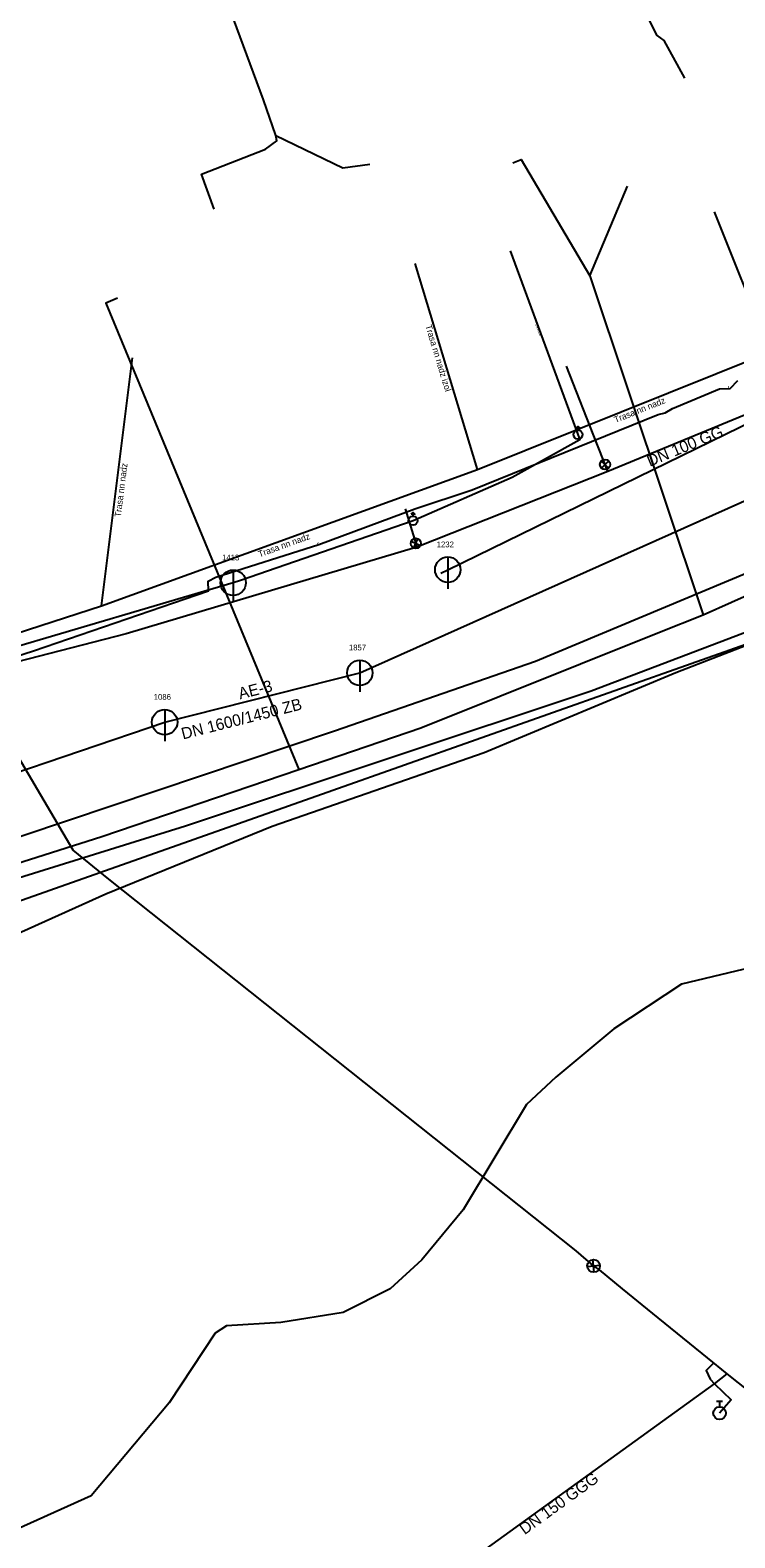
# Model space of a CAD drawing. Extents: x -493753 to -49291, y -1127285 to -112662.
# Drawn here: x -493148.8 to -493093.4, y -1126714.4 to -1126595.6 of the extents above; entities that cross this region are included whole.
import ezdxf

# ---------------------------------------------------------------- set-up
doc = ezdxf.new("R2010")
doc.units = 0
for name, color, linetype in [('Vrstva 1', 7, 'Continuous'), ('Vrstva 15', 7, 'Continuous'), ('Vrstva 17', 7, 'Continuous'), ('Vrstva 19', 7, 'Continuous'), ('Vrstva 20', 7, 'Continuous'), ('Vrstva 22', 7, 'Continuous'), ('Vrstva 24', 7, 'Continuous'), ('Vrstva 25', 7, 'Continuous'), ('Vrstva 26', 7, 'Continuous'), ('Vrstva 39', 7, 'Continuous'), ('Vrstva 5', 7, 'Continuous'), ('Vrstva 6', 7, 'Continuous'), ('Vrstva 9', 7, 'Continuous')]:
    doc.layers.add(name, color=color, linetype=linetype)

# ---------------------------------------------------------------- blocks, each defined once
blk = doc.blocks.new('_UZAVE')
at = {"layer": 'Vrstva 1'}
for p, q in [((-0.035, -0.035), (0.035, 0.035)), ((0.035, -0.035), (-0.035, 0.035))]:
    blk.add_line(p, q, dxfattribs=at)
for radius in [0.05, 0.0025]:
    blk.add_circle((0, 0), radius, dxfattribs=at)
blk = doc.blocks.new('_UZAV0')
at = {"layer": 'Vrstva 1'}
for p, q in [((-0.035, -0.035), (0.035, 0.035)), ((0.035, -0.035), (-0.035, 0.035))]:
    blk.add_line(p, q, dxfattribs=at)
for radius in [0.05, 0.0025]:
    blk.add_circle((0, 0), radius, dxfattribs=at)
blk = doc.blocks.new('_HYDRA')
at = {"layer": 'Vrstva 1'}
for p, q in [((-0.0225, 0.095), (0.0225, 0.095)), ((0, 0.095), (0, 0.05))]:
    blk.add_line(p, q, dxfattribs=at)
blk.add_circle((0, 0), 0.05, dxfattribs=at)
blk = doc.blocks.new('_SACHT')
at = {"layer": 'Vrstva 1'}
blk.add_line((0, 0.035), (0, 0.05), dxfattribs=at)
blk.add_lwpolyline([(-0.015, 0.05), (0, 0.065), (0.015, 0.05), (0.0025, 0.05)], close=True, dxfattribs=at)
blk.add_circle((0, 0), 0.035, dxfattribs=at)
blk = doc.blocks.new('_SACH0')
at = {"layer": 'Vrstva 1'}
blk.add_line((0, 0.05), (0, -0.075), dxfattribs=at)
blk.add_circle((0, 0), 0.05, dxfattribs=at)

msp = doc.modelspace()

# ---------------------------------------------------------------- linework, layer by layer
at = {"layer": 'Vrstva 1'}
for q in [(-493101.8, -1126607.9), (-493095.87, -1126641.67)]:
    msp.add_line((-493104.79, -1126614.96), q, dxfattribs=at)
for points in [[(-493386.97, -1126735.58), (-493385.48, -1126734.62), (-493337.07, -1126719.76), (-493332.99, -1126718.51), (-493329.52, -1126722.33), (-493310.17, -1126716.12), (-493297.1, -1126711.97), (-493263.47, -1126701.76), (-493238.75, -1126693.15), (-493207.17, -1126683.67), (-493191.4, -1126678.95), (-493125, -1126655.47), (-493062.97, -1126633.54), (-492997.53, -1126590.18)], [(-493110.83, -1126606.06), (-493110.18, -1126605.8), (-493104.79, -1126614.96)], [(-493141.96, -1126616.73), (-493142.88, -1126617.12), (-493127.68, -1126653.85)], [(-493385.61, -1126724.05), (-493194.98, -1126660.12), (-493187.12, -1126657.48), (-493186.67, -1126658.59), (-493182.04, -1126669.95), (-493181.8, -1126670.54), (-493154.52, -1126662.73), (-493143.18, -1126659.14), (-493127.68, -1126653.85), (-493118.08, -1126650.58), (-493099.29, -1126643.04), (-493095.87, -1126641.67), (-493086.94, -1126637.67)]]:
    msp.add_lwpolyline(points, dxfattribs=at)
at = {"layer": 'Vrstva 15'}
for p, q in [((-493115.96, -1126638.11), (-493046.27, -1126604.06)), ((-493122.88, -1126646.24), (-493045.09, -1126611.4)), ((-493111.06, -1126612.99), (-493105.71, -1126627.47)), ((-493118.69, -1126634.25), (-493132.28, -1126638.97)), ((-493132.28, -1126638.97), (-493132.85, -1126639.14)), ((-493116.5, -1126638.38), (-493115.96, -1126638.11)), ((-493132.85, -1126639.14), (-493171.26, -1126650.48)), ((-493138.24, -1126650.12), (-493122.88, -1126646.24)), ((-493211.56, -1126675.07), (-493138.24, -1126650.12))]:
    msp.add_line(p, q, dxfattribs=at)
msp.add_lwpolyline([(-493105.71, -1126627.47), (-493105.56, -1126627.88), (-493110.88, -1126630.84), (-493118.69, -1126634.25)], dxfattribs=at)
at = {"layer": 'Vrstva 20'}
for p, q in [((-493094.98, -1126609.92), (-493090.33, -1126621.6)), ((-493104.23, -1126628.16), (-493106.62, -1126622.08)), ((-493091.16, -1126703.69), (-493093.97, -1126701.44))]:
    msp.add_line(p, q, dxfattribs=at)
for points in [[(-493174.97, -1126671), (-493168.95, -1126668.59), (-493150.92, -1126662.76), (-493136.6, -1126658.3), (-493104.67, -1126647.66), (-493085.83, -1126640.49), (-493075.06, -1126636.63), (-493066.87, -1126632.41), (-493057.12, -1126625.67), (-493040.16, -1126614.7), (-493027.86, -1126606.78), (-493012.63, -1126597.22), (-493006.68, -1126593.57), (-492997.84, -1126587.96), (-492995.32, -1126586.25), (-492988.81, -1126582.57), (-492979.95, -1126576.81), (-492978.81, -1126576)], [(-493104.48, -1126692.95), (-493105.85, -1126691.77), (-493142.64, -1126662.49), (-493145.44, -1126660.21), (-493155.3, -1126643.44), (-493158.9, -1126637.17), (-493179.3, -1126603.57)], [(-493085.26, -1126622.7), (-493089.17, -1126624.53), (-493103.36, -1126630.39), (-493118.4, -1126636.33), (-493141.27, -1126643.17), (-493154.23, -1126646.51)], [(-493103.36, -1126630.39), (-493103.58, -1126629.83), (-493104.23, -1126628.16)], [(-493119.3, -1126633.31), (-493118.47, -1126636.04), (-493118.4, -1126636.33)], [(-493093.97, -1126701.44), (-493095.52, -1126700.19), (-493099.83, -1126696.7), (-493102.2, -1126694.76), (-493104.01, -1126693.25), (-493104.48, -1126692.95)], [(-493095.03, -1126700.59), (-493095.61, -1126701.2), (-493095.31, -1126701.88), (-493094.96, -1126702.23), (-493093.66, -1126703.5), (-493094.57, -1126704.55)], [(-493119.65, -1126720.09), (-493094.96, -1126702.23), (-493093.97, -1126701.44)]]:
    msp.add_lwpolyline(points, dxfattribs=at)
at = {"layer": 'Vrstva 25'}
msp.add_lwpolyline([(-493164.43, -1126646.67), (-493163.94, -1126647.33), (-493163.37, -1126647.77), (-493156.2, -1126645.58), (-493155.46, -1126646.71), (-493148.57, -1126644.5), (-493134.79, -1126639.78), (-493134.82, -1126639.02), (-493134.2, -1126638.71), (-493126.11, -1126636.12), (-493118.54, -1126633.31), (-493114.04, -1126631.81), (-493099.4, -1126625.88), (-493098.84, -1126625.76), (-493098.28, -1126625.42), (-493094.57, -1126623.87), (-493093.74, -1126623.83), (-493093.12, -1126623.22)], dxfattribs=at)
at = {"layer": 'Vrstva 26'}
for p, q in [((-493093.86, -1126623.7), (-493093.83, -1126623.71)), ((-493126.2, -1126636), (-493126.19, -1126636.03))]:
    msp.add_line(p, q, dxfattribs=at)
at = {"layer": 'Vrstva 39'}
for points in [[(-493106.41, -1126581.97), (-493105.81, -1126583.16), (-493099.52, -1126596.02), (-493098.96, -1126596.44), (-493097.32, -1126599.39)], [(-493129.5, -1126603.92), (-493130.46, -1126601.1), (-493133.09, -1126594.02), (-493134.58, -1126590.32)], [(-493134.35, -1126609.71), (-493135.34, -1126606.95), (-493130.31, -1126605), (-493129.42, -1126604.33), (-493129.5, -1126603.92)], [(-493129.5, -1126603.92), (-493124.21, -1126606.47), (-493122.1, -1126606.16)], [(-493156.38, -1126661.38), (-493124.88, -1126650.8), (-493109.06, -1126645.32), (-493090.65, -1126637.63), (-493079.53, -1126633.19)], [(-493081.08, -1126639.68), (-493098.01, -1126646.24), (-493113.1, -1126652.55), (-493129.78, -1126658.33), (-493142.88, -1126663.67), (-493151.41, -1126667.51), (-493153.5, -1126667.92), (-493155.32, -1126667.23)]]:
    msp.add_lwpolyline(points, dxfattribs=at)
at = {"layer": 'Vrstva 5'}
for points in [[(-493113.63, -1126630.23), (-493118.53, -1126613.99)], [(-493113.63, -1126630.23), (-493087.29, -1126619.65)], [(-493143.22, -1126640.97), (-493140.77, -1126621.43)], [(-493143.22, -1126640.97), (-493113.63, -1126630.23)], [(-493173.25, -1126650.69), (-493143.22, -1126640.97)]]:
    msp.add_lwpolyline(points, dxfattribs=at)
at = {"layer": 'Vrstva 6'}
msp.add_lwpolyline([(-493089.02, -1126668.7), (-493097.55, -1126670.77), (-493102.89, -1126674.28), (-493107.46, -1126678.08), (-493109.76, -1126680.24), (-493114.75, -1126688.53), (-493118.01, -1126692.46), (-493120.49, -1126694.75), (-493124.18, -1126696.61), (-493129.09, -1126697.4), (-493133.38, -1126697.66), (-493134.27, -1126698.24), (-493137.89, -1126703.73), (-493144.02, -1126711.06), (-493158.37, -1126717.52), (-493159.88, -1126717.4)], dxfattribs=at)

# ---------------------------------------------------------------- block references
at = {"layer": 'Vrstva 17'}
for name, p, xscale, yscale in [('_SACHT', (-493105.71, -1126627.47), 9.998750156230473, 9.998750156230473), ('_SACHT', (-493118.69, -1126634.25), 9.998750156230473, 9.998750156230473), ('_SACH0', (-493115.96, -1126638.11), 19.997500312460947, 19.997500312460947), ('_SACH0', (-493132.85, -1126639.14), 19.997500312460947, 19.997500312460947), ('_SACH0', (-493122.88, -1126646.24), 19.997500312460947, 19.997500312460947), ('_SACH0', (-493138.24, -1126650.12), 19.997500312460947, 19.997500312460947)]:
    msp.add_blockref(name, p, dxfattribs=dict(at, xscale=xscale, yscale=yscale))
at = {"layer": 'Vrstva 22'}
for name, p, xscale, yscale in [('_UZAV0', (-493103.58, -1126629.83), 7.999000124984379, 7.999000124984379), ('_HYDRA', (-493094.57, -1126704.55), 9.998750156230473, 9.998750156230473)]:
    msp.add_blockref(name, p, dxfattribs=dict(at, xscale=xscale, yscale=yscale))
for name, p, xscale, yscale, rotation in [('_UZAV0', (-493118.47, -1126636.04), 7.999000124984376, 7.999000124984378, -69.302497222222), ('_UZAVE', (-493104.48, -1126692.95), 9.998750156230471, 9.998750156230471, -38.70192013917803)]:
    msp.add_blockref(name, p, dxfattribs=dict(at, xscale=xscale, yscale=yscale, rotation=rotation))

# ---------------------------------------------------------------- texts
at = {"layer": 'Vrstva 19'}
for s, height, rotation, p in [('DN 200 B', 0.16, 290.3089, (-493109.08, -1126618.81)), ('AE-3', 0.91, 14.1915, (-493132.31, -1126648.33)), ('DN 1600/1450 ZB', 0.9099, 14.1915, (-493136.8, -1126651.49))]:
    msp.add_text(s, height=height, rotation=rotation, dxfattribs=at).set_placement(p)
for s, p in [('1232', (-493116.83, -1126636.35)), ('1413', (-493133.72, -1126637.38)), ('1857', (-493123.74, -1126644.47)), ('1086', (-493139.1, -1126648.36))]:
    msp.add_text(s, height=0.455, dxfattribs=at).set_placement(p)
at = {"layer": 'Vrstva 24'}
for s, rotation, p in [('DN 100 GG', 22.4344, (-493100.06, -1126630.01)), ('DN 150 GGG', 35.8788, (-493109.91, -1126714.16))]:
    msp.add_text(s, height=0.91, rotation=rotation, dxfattribs=at).set_placement(p)
at = {"layer": 'Vrstva 9'}
for s, rotation, p in [('Trasa nn nadz izol', 286.7839, (-493117.73, -1126618.9)), ('Trasa nn nadz', 21.8801, (-493102.75, -1126626.56)), ('Trasa nn nadz', 82.8582, (-493141.69, -1126633.99)), ('Trasa nn nadz', 19.9525, (-493130.77, -1126637.14))]:
    msp.add_text(s, height=0.5, rotation=rotation, dxfattribs=at).set_placement(p)

doc.saveas('drawing.dxf')
